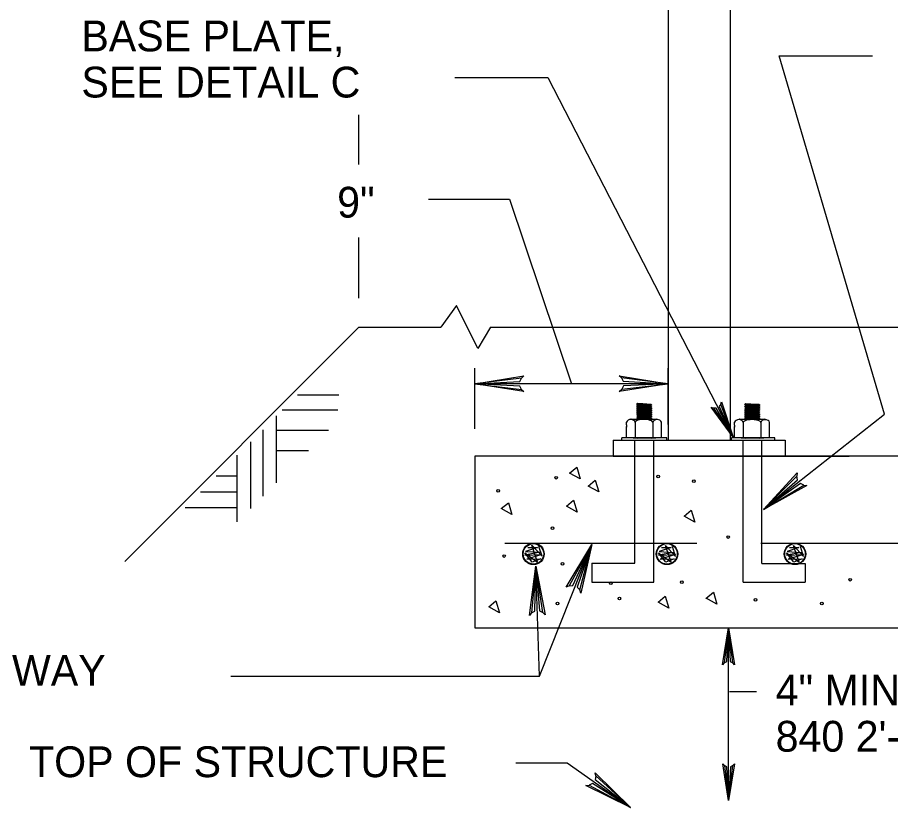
# Model space of a CAD drawing. Extents: x 637628 to 640188, y 298266 to 300751.
# Drawn here: x 638042.5 to 638127.6, y 298943.4 to 299020.4 of the extents above; entities that cross this region are included whole.
import ezdxf

# ---------------------------------------------------------------- set-up
doc = ezdxf.new("R2010")
doc.units = 0
for name, color, linetype in [('1', 7, 'Continuous'), ('2', 7, 'Continuous'), ('3', 7, 'Continuous')]:
    doc.layers.add(name, color=color, linetype=linetype)

msp = doc.modelspace()

# ---------------------------------------------------------------- linework, layer by layer
at = {"layer": '1'}
for p, q in [((638127.052, 298981.742), (638116.764, 299016.653)), ((638115.246, 298972.466), (638127.052, 298981.742))]:
    msp.add_line(p, q, dxfattribs=at)
at = {"layer": '2'}
for p, q in [((638105.949, 299059.25), (638105.949, 298979.219)), ((638105.949, 299059.25), (638105.949, 298979.219)), ((638111.99, 299059.25), (638111.99, 298979.219)), ((638111.99, 299059.25), (638111.99, 298979.219)), ((638116.764, 299016.653), (638125.872, 299016.653)), ((638085.156, 299014.527), (638094.215, 299014.527)), ((638094.215, 299014.527), (638112.272, 298979.5)), ((638075.776, 299006.064), (638075.776, 299010.894)), ((638082.581, 299002.68), (638090.48, 299002.68)), ((638090.48, 299002.68), (638096.54, 298984.707)), ((638075.776, 298993.04), (638075.776, 298998.948)), ((638085.313, 298992.317), (638083.784, 298990.205)), ((638085.313, 298992.317), (638083.784, 298990.205)), ((638087.407, 298988.136), (638085.313, 298992.317)), ((638087.407, 298988.136), (638085.313, 298992.317)), ((638075.776, 298990.205), (638052.972, 298967.4)), ((638075.776, 298990.205), (638083.784, 298990.205)), ((638075.776, 298990.205), (638083.784, 298990.205)), ((638088.632, 298990.205), (638087.407, 298988.136)), ((638088.632, 298990.205), (638087.407, 298988.136)), ((638088.632, 298990.205), (638220.882, 298990.205)), ((638088.632, 298990.205), (638207.774, 298990.205)), ((638118.24, 298990.205), (638123.599, 298990.205)), ((638118.24, 298990.205), (638123.599, 298990.205)), ((638087.115, 298980.317), (638087.115, 298986.207)), ((638105.949, 298980.719), (638105.949, 298986.207)), ((638105.949, 298984.707), (638087.115, 298984.707)), ((638073.826, 298983.575), (638069.813, 298983.575)), ((638073.826, 298983.575), (638069.813, 298983.575)), ((638102.953, 298982.767), (638102.897, 298982.734)), ((638102.897, 298982.734), (638104.345, 298982.661)), ((638102.897, 298982.709), (638104.345, 298982.638)), ((638102.897, 298982.709), (638102.999, 298982.648)), ((638102.953, 298982.575), (638102.897, 298982.542)), ((638102.999, 298982.794), (638102.953, 298982.767)), ((638102.999, 298982.602), (638102.953, 298982.575)), ((638102.999, 298982.794), (638103.474, 298982.767)), ((638102.999, 298982.648), (638104.242, 298982.575)), ((638102.999, 298982.648), (638104.242, 298982.575)), ((638102.999, 298982.602), (638103.474, 298982.575)), ((638103.474, 298982.767), (638104.242, 298982.723)), ((638103.474, 298982.575), (638104.242, 298982.532)), ((638104.242, 298982.723), (638104.345, 298982.661)), ((638104.345, 298982.638), (638104.242, 298982.575)), ((638104.345, 298982.638), (638104.345, 298982.661)), ((638113.484, 298982.752), (638113.428, 298982.719)), ((638113.428, 298982.719), (638114.876, 298982.646)), ((638113.428, 298982.694), (638114.876, 298982.623)), ((638113.428, 298982.694), (638113.53, 298982.634)), ((638113.484, 298982.561), (638113.428, 298982.527)), ((638113.53, 298982.78), (638113.484, 298982.752)), ((638113.53, 298982.588), (638113.484, 298982.561)), ((638113.53, 298982.78), (638114.005, 298982.752)), ((638113.53, 298982.634), (638114.774, 298982.561)), ((638113.53, 298982.634), (638114.774, 298982.561)), ((638113.53, 298982.588), (638114.005, 298982.561)), ((638114.005, 298982.752), (638114.774, 298982.709)), ((638114.005, 298982.561), (638114.774, 298982.517)), ((638114.774, 298982.709), (638114.876, 298982.646)), ((638114.876, 298982.623), (638114.774, 298982.561)), ((638114.876, 298982.623), (638114.876, 298982.646)), ((638073.73, 298982.132), (638068.317, 298982.132)), ((638073.73, 298982.132), (638068.317, 298982.132)), ((638102.897, 298982.542), (638104.345, 298982.469)), ((638102.897, 298982.519), (638104.345, 298982.446)), ((638102.897, 298982.519), (638102.999, 298982.457)), ((638102.953, 298982.386), (638102.897, 298982.35)), ((638102.897, 298982.35), (638104.345, 298982.28)), ((638102.897, 298982.327), (638104.345, 298982.255)), ((638102.897, 298982.327), (638102.999, 298982.265)), ((638102.953, 298982.194), (638102.897, 298982.161)), ((638102.897, 298982.161), (638104.345, 298982.088)), ((638102.897, 298982.136), (638104.345, 298982.065)), ((638102.897, 298982.136), (638102.999, 298982.075)), ((638102.953, 298982.002), (638102.897, 298981.969)), ((638102.897, 298981.969), (638104.345, 298981.898)), ((638102.897, 298981.946), (638104.345, 298981.873)), ((638102.897, 298981.946), (638102.999, 298981.884)), ((638102.953, 298981.813), (638102.897, 298981.78)), ((638102.897, 298981.78), (638104.345, 298981.707)), ((638102.897, 298981.755), (638104.345, 298981.684)), ((638102.897, 298981.755), (638102.999, 298981.694)), ((638102.999, 298982.413), (638102.953, 298982.386)), ((638102.999, 298982.221), (638102.953, 298982.194)), ((638102.999, 298982.032), (638102.953, 298982.002)), ((638102.999, 298981.84), (638102.953, 298981.813)), ((638102.999, 298982.457), (638104.242, 298982.386)), ((638102.999, 298982.457), (638104.242, 298982.386)), ((638102.999, 298982.413), (638103.474, 298982.386)), ((638102.999, 298982.265), (638104.242, 298982.194)), ((638102.999, 298982.265), (638104.242, 298982.194)), ((638102.999, 298982.221), (638103.474, 298982.194)), ((638102.999, 298982.075), (638104.242, 298982.002)), ((638102.999, 298982.075), (638104.242, 298982.002)), ((638102.999, 298982.032), (638103.474, 298982.002)), ((638102.999, 298981.884), (638104.242, 298981.813)), ((638102.999, 298981.884), (638104.242, 298981.813)), ((638102.999, 298981.84), (638103.474, 298981.813)), ((638102.999, 298981.694), (638104.242, 298981.621)), ((638102.999, 298981.694), (638104.242, 298981.621)), ((638103.474, 298982.386), (638104.242, 298982.34)), ((638103.474, 298982.194), (638104.242, 298982.15)), ((638103.474, 298982.002), (638104.242, 298981.959)), ((638103.474, 298981.813), (638104.242, 298981.769)), ((638104.242, 298982.532), (638104.345, 298982.469)), ((638104.345, 298982.446), (638104.242, 298982.386)), ((638104.242, 298982.34), (638104.345, 298982.28)), ((638104.345, 298982.255), (638104.242, 298982.194)), ((638104.242, 298982.15), (638104.345, 298982.088)), ((638104.345, 298982.065), (638104.242, 298982.002)), ((638104.242, 298981.959), (638104.345, 298981.898)), ((638104.345, 298981.873), (638104.242, 298981.813)), ((638104.242, 298981.769), (638104.345, 298981.707)), ((638104.345, 298982.446), (638104.345, 298982.469)), ((638104.345, 298982.255), (638104.345, 298982.28)), ((638104.345, 298982.065), (638104.345, 298982.088)), ((638104.345, 298981.873), (638104.345, 298981.898)), ((638104.345, 298981.684), (638104.345, 298981.707)), ((638113.428, 298982.527), (638114.876, 298982.457)), ((638113.428, 298982.502), (638114.876, 298982.432)), ((638113.428, 298982.502), (638113.53, 298982.442)), ((638113.484, 298982.371), (638113.428, 298982.336)), ((638113.428, 298982.336), (638114.876, 298982.265)), ((638113.428, 298982.313), (638114.876, 298982.24)), ((638113.428, 298982.313), (638113.53, 298982.25)), ((638113.484, 298982.18), (638113.428, 298982.146)), ((638113.428, 298982.146), (638114.876, 298982.073)), ((638113.428, 298982.121), (638114.876, 298982.05)), ((638113.428, 298982.121), (638113.53, 298982.061)), ((638113.484, 298981.988), (638113.428, 298981.955)), ((638113.428, 298981.955), (638114.876, 298981.884)), ((638113.428, 298981.932), (638114.876, 298981.859)), ((638113.428, 298981.932), (638113.53, 298981.869)), ((638113.484, 298981.798), (638113.428, 298981.763)), ((638113.428, 298981.763), (638114.876, 298981.692)), ((638113.428, 298981.74), (638114.876, 298981.669)), ((638113.428, 298981.74), (638113.53, 298981.677)), ((638113.53, 298982.398), (638113.484, 298982.371)), ((638113.53, 298982.207), (638113.484, 298982.18)), ((638113.53, 298982.017), (638113.484, 298981.988)), ((638113.53, 298981.825), (638113.484, 298981.798)), ((638113.53, 298982.442), (638114.774, 298982.371)), ((638113.53, 298982.442), (638114.774, 298982.371)), ((638113.53, 298982.398), (638114.005, 298982.371)), ((638113.53, 298982.25), (638114.774, 298982.18)), ((638113.53, 298982.25), (638114.774, 298982.18)), ((638113.53, 298982.207), (638114.005, 298982.18)), ((638113.53, 298982.061), (638114.774, 298981.988)), ((638113.53, 298982.061), (638114.774, 298981.988)), ((638113.53, 298982.017), (638114.005, 298981.988)), ((638113.53, 298981.869), (638114.774, 298981.798)), ((638113.53, 298981.869), (638114.774, 298981.798)), ((638113.53, 298981.825), (638114.005, 298981.798)), ((638114.005, 298982.371), (638114.774, 298982.325)), ((638114.005, 298982.18), (638114.774, 298982.136)), ((638114.005, 298981.988), (638114.774, 298981.944)), ((638114.005, 298981.798), (638114.774, 298981.755)), ((638114.774, 298982.517), (638114.876, 298982.457)), ((638114.876, 298982.432), (638114.774, 298982.371)), ((638114.774, 298982.325), (638114.876, 298982.265)), ((638114.876, 298982.24), (638114.774, 298982.18)), ((638114.774, 298982.136), (638114.876, 298982.073)), ((638114.876, 298982.05), (638114.774, 298981.988)), ((638114.774, 298981.944), (638114.876, 298981.884)), ((638114.876, 298981.859), (638114.774, 298981.798)), ((638114.774, 298981.755), (638114.876, 298981.692)), ((638114.876, 298982.432), (638114.876, 298982.457)), ((638114.876, 298982.24), (638114.876, 298982.265)), ((638114.876, 298982.05), (638114.876, 298982.073)), ((638114.876, 298981.859), (638114.876, 298981.884)), ((638067.751, 298975.044), (638067.751, 298981.565)), ((638067.751, 298975.044), (638067.751, 298981.565)), ((638101.89, 298980.688), (638101.89, 298980.963)), ((638102.357, 298981.267), (638104.83, 298981.267)), ((638102.73, 298980.94), (638102.73, 298979.442)), ((638102.953, 298981.621), (638102.897, 298981.588)), ((638102.897, 298981.588), (638104.345, 298981.515)), ((638102.897, 298981.563), (638104.345, 298981.492)), ((638102.897, 298981.563), (638102.999, 298981.502)), ((638102.953, 298981.432), (638102.897, 298981.396)), ((638102.897, 298981.396), (638104.345, 298981.325)), ((638102.897, 298981.373), (638104.345, 298981.3)), ((638102.897, 298981.373), (638102.999, 298981.311)), ((638102.999, 298981.648), (638102.953, 298981.621)), ((638102.999, 298981.459), (638102.953, 298981.432)), ((638102.999, 298981.267), (638102.953, 298981.24)), ((638102.999, 298981.648), (638103.474, 298981.621)), ((638102.999, 298981.502), (638104.242, 298981.432)), ((638102.999, 298981.502), (638104.242, 298981.432)), ((638102.999, 298981.459), (638103.474, 298981.432)), ((638102.999, 298981.311), (638104.242, 298981.24)), ((638102.999, 298981.311), (638104.242, 298981.24)), ((638102.999, 298981.267), (638103.474, 298981.24)), ((638103.474, 298981.621), (638104.242, 298981.577)), ((638103.474, 298981.432), (638104.242, 298981.386)), ((638104.345, 298981.684), (638104.242, 298981.621)), ((638104.242, 298981.577), (638104.345, 298981.515)), ((638104.345, 298981.492), (638104.242, 298981.432)), ((638104.242, 298981.386), (638104.345, 298981.325)), ((638104.345, 298981.3), (638104.242, 298981.24)), ((638104.345, 298981.492), (638104.345, 298981.515)), ((638104.345, 298981.3), (638104.345, 298981.325)), ((638104.457, 298980.932), (638104.457, 298979.442)), ((638105.295, 298979.442), (638105.295, 298980.952)), ((638112.422, 298980.673), (638112.422, 298980.948)), ((638112.888, 298981.252), (638115.361, 298981.252)), ((638113.261, 298980.925), (638113.261, 298979.427)), ((638113.484, 298981.607), (638113.428, 298981.573)), ((638113.428, 298981.573), (638114.876, 298981.5)), ((638113.428, 298981.548), (638114.876, 298981.477)), ((638113.428, 298981.548), (638113.53, 298981.488)), ((638113.484, 298981.415), (638113.428, 298981.382)), ((638113.428, 298981.382), (638114.876, 298981.311)), ((638113.428, 298981.359), (638114.876, 298981.286)), ((638113.428, 298981.359), (638113.53, 298981.296)), ((638113.53, 298981.634), (638113.484, 298981.607)), ((638113.53, 298981.444), (638113.484, 298981.415)), ((638113.53, 298981.252), (638113.484, 298981.225)), ((638113.53, 298981.677), (638114.774, 298981.607)), ((638113.53, 298981.677), (638114.774, 298981.607)), ((638113.53, 298981.634), (638114.005, 298981.607)), ((638113.53, 298981.488), (638114.774, 298981.415)), ((638113.53, 298981.488), (638114.774, 298981.415)), ((638113.53, 298981.444), (638114.005, 298981.415)), ((638113.53, 298981.296), (638114.774, 298981.225)), ((638113.53, 298981.296), (638114.774, 298981.225)), ((638113.53, 298981.252), (638114.005, 298981.225)), ((638114.005, 298981.607), (638114.774, 298981.563)), ((638114.005, 298981.415), (638114.774, 298981.371)), ((638114.876, 298981.669), (638114.774, 298981.607)), ((638114.774, 298981.563), (638114.876, 298981.5)), ((638114.876, 298981.477), (638114.774, 298981.415)), ((638114.774, 298981.371), (638114.876, 298981.311)), ((638114.876, 298981.286), (638114.774, 298981.225)), ((638114.876, 298981.669), (638114.876, 298981.692)), ((638114.876, 298981.477), (638114.876, 298981.5)), ((638114.876, 298981.286), (638114.876, 298981.311)), ((638114.988, 298980.917), (638114.988, 298979.427)), ((638115.826, 298979.427), (638115.826, 298980.938)), ((638066.451, 298973.738), (638066.451, 298980.215)), ((638066.451, 298973.738), (638066.451, 298980.215)), ((638072.847, 298980.132), (638067.811, 298980.132)), ((638072.847, 298980.132), (638067.811, 298980.132)), ((638101.89, 298980.688), (638101.89, 298980.488)), ((638101.89, 298979.442), (638101.89, 298980.546)), ((638112.422, 298980.673), (638112.422, 298980.471)), ((638112.422, 298979.427), (638112.422, 298980.532)), ((638100.584, 298979.219), (638100.584, 298977.65)), ((638100.584, 298979.219), (638100.584, 298977.65)), ((638100.584, 298979.219), (638105.57, 298979.219)), ((638100.584, 298979.219), (638101.884, 298979.219)), ((638105.815, 298979.442), (638101.44, 298979.442)), ((638101.44, 298979.242), (638101.44, 298979.442)), ((638102.534, 298979.444), (638104.751, 298979.444)), ((638102.534, 298979.444), (638104.751, 298979.444)), ((638102.709, 298967.217), (638102.709, 298979.215)), ((638102.709, 298967.217), (638102.709, 298979.215)), ((638102.897, 298979.463), (638102.999, 298979.402)), ((638104.242, 298979.477), (638104.345, 298979.417)), ((638104.54, 298965.367), (638104.54, 298979.215)), ((638104.54, 298967.207), (638104.54, 298979.215)), ((638105.57, 298979.219), (638117.349, 298979.219)), ((638105.57, 298979.219), (638117.349, 298979.219)), ((638105.815, 298979.248), (638105.815, 298979.442)), ((638116.349, 298979.427), (638112.111, 298979.427)), ((638112.111, 298979.248), (638112.111, 298979.427)), ((638113.065, 298979.43), (638115.282, 298979.43)), ((638113.065, 298979.43), (638115.282, 298979.43)), ((638113.249, 298967.188), (638113.249, 298979.223)), ((638113.249, 298965.363), (638113.249, 298979.213)), ((638113.428, 298979.45), (638113.53, 298979.388)), ((638114.774, 298979.463), (638114.876, 298979.402)), ((638115.082, 298967.188), (638115.082, 298979.223)), ((638115.082, 298967.188), (638115.082, 298979.223)), ((638116.349, 298979.234), (638116.349, 298979.427)), ((638117.349, 298979.219), (638117.349, 298977.65)), ((638065.272, 298972.557), (638065.272, 298979.034)), ((638065.272, 298972.557), (638065.272, 298979.034)), ((638063.942, 298971.236), (638063.945, 298977.757)), ((638063.942, 298971.236), (638063.945, 298977.757)), ((638070.895, 298978.18), (638067.838, 298978.18)), ((638070.895, 298978.18), (638067.838, 298978.18)), ((638100.584, 298977.65), (638123.599, 298977.65)), ((638100.584, 298977.65), (638123.599, 298977.65)), ((638063.936, 298975.696), (638061.884, 298975.696)), ((638063.936, 298975.696), (638061.884, 298975.696)), ((638063.959, 298974.13), (638060.365, 298974.13)), ((638063.959, 298974.13), (638060.365, 298974.13)), ((638063.934, 298972.611), (638058.849, 298972.611)), ((638063.934, 298972.611), (638058.849, 298972.611)), ((638090.011, 298969.177), (638108.742, 298969.177)), ((638093.224, 298967.321), (638092.655, 298968.961)), ((638092.655, 298968.961), (638093.655, 298967.89)), ((638092.815, 298969.177), (638105.892, 298969.177)), ((638106.245, 298967.315), (638105.676, 298968.955)), ((638105.676, 298968.955), (638106.676, 298967.886)), ((638114.986, 298969.177), (638134.967, 298969.177)), ((638118.722, 298967.315), (638118.151, 298968.955)), ((638118.151, 298968.955), (638119.151, 298967.886)), ((638118.274, 298969.177), (638131.351, 298969.177)), ((638093.463, 298968.282), (638091.984, 298968)), ((638092.695, 298967.321), (638091.984, 298968.232)), ((638091.984, 298968.232), (638093.224, 298967.321)), ((638093.205, 298968.75), (638092.055, 298968.361)), ((638092.055, 298968.361), (638093.463, 298968.282)), ((638092.263, 298968.75), (638093.205, 298968.75)), ((638092.813, 298968.132), (638092.813, 298968.132)), ((638093.655, 298967.89), (638093.355, 298968.861)), ((638106.484, 298968.275), (638105.005, 298967.994)), ((638105.715, 298967.315), (638105.005, 298968.225)), ((638105.005, 298968.225), (638106.245, 298967.315)), ((638106.226, 298968.744), (638105.076, 298968.355)), ((638105.076, 298968.355), (638106.484, 298968.275)), ((638105.284, 298968.744), (638106.226, 298968.744)), ((638105.834, 298968.125), (638105.834, 298968.125)), ((638106.676, 298967.886), (638106.376, 298968.855)), ((638118.961, 298968.275), (638117.482, 298967.996)), ((638118.192, 298967.315), (638117.482, 298968.225)), ((638117.482, 298968.225), (638118.722, 298967.315)), ((638118.701, 298968.746), (638117.551, 298968.355)), ((638117.551, 298968.355), (638118.961, 298968.275)), ((638117.761, 298968.746), (638118.701, 298968.746)), ((638118.311, 298968.125), (638118.311, 298968.125)), ((638119.151, 298967.886), (638118.851, 298968.855)), ((638091.984, 298968), (638093.634, 298968.061)), ((638093.634, 298968.061), (638092.163, 298967.611)), ((638092.163, 298967.611), (638093.524, 298967.64)), ((638093.524, 298967.64), (638092.695, 298967.321)), ((638105.005, 298967.994), (638106.655, 298968.055)), ((638106.655, 298968.055), (638105.184, 298967.605)), ((638105.184, 298967.605), (638106.545, 298967.636)), ((638106.545, 298967.636), (638105.715, 298967.315)), ((638117.482, 298967.996), (638119.132, 298968.055)), ((638119.132, 298968.055), (638117.661, 298967.605)), ((638117.661, 298967.605), (638119.022, 298967.636)), ((638119.022, 298967.636), (638118.192, 298967.315)), ((638098.497, 298967.217), (638098.497, 298965.367)), ((638098.497, 298967.217), (638102.709, 298967.217)), ((638115.082, 298967.188), (638119.292, 298967.188)), ((638119.292, 298967.188), (638119.292, 298965.363)), ((638098.497, 298965.367), (638104.54, 298965.367)), ((638113.249, 298965.363), (638119.292, 298965.363)), ((638087.115, 298960.913), (638187.549, 298960.913)), ((638111.838, 298944.105), (638111.838, 298960.913)), ((638111.929, 298954.713), (638114.567, 298954.713))]:
    msp.add_line(p, q, dxfattribs=at)
for points in [[(638091.657, 298984.136), (638091.488, 298984.465), (638087.115, 298984.707), (638091.657, 298984.136), (638091.89, 298983.936), (638087.115, 298984.707), (638091.484, 298984.921), (638091.645, 298985.246), (638087.115, 298984.707), (638091.89, 298985.465), (638091.645, 298985.246)], [(638101.407, 298985.275), (638101.576, 298984.946), (638105.949, 298984.707), (638101.407, 298985.275), (638101.174, 298985.475), (638105.949, 298984.707), (638101.58, 298984.49), (638101.42, 298984.165), (638105.949, 298984.707), (638101.174, 298983.946), (638101.42, 298984.165)], [(638102.897, 298982.709), (638102.897, 298982.734)], [(638102.999, 298982.602), (638102.999, 298982.648)], [(638104.242, 298982.532), (638104.242, 298982.575)], [(638111.09, 298982.723), (638110.93, 298982.496), (638112.272, 298979.5), (638111.09, 298982.723), (638111.145, 298982.946), (638112.272, 298979.5), (638110.626, 298982.338), (638110.355, 298982.332), (638112.272, 298979.5), (638110.126, 298982.421), (638110.355, 298982.332)], [(638113.428, 298982.694), (638113.428, 298982.719)], [(638113.53, 298982.588), (638113.53, 298982.634)], [(638114.774, 298982.517), (638114.774, 298982.561)], [(638102.897, 298982.519), (638102.897, 298982.542)], [(638102.897, 298982.327), (638102.897, 298982.35)], [(638102.897, 298982.136), (638102.897, 298982.161)], [(638102.897, 298981.946), (638102.897, 298981.969)], [(638102.897, 298981.755), (638102.897, 298981.78)], [(638102.999, 298982.413), (638102.999, 298982.457)], [(638102.999, 298982.221), (638102.999, 298982.265)], [(638102.999, 298982.032), (638102.999, 298982.075)], [(638102.999, 298981.84), (638102.999, 298981.884)], [(638102.999, 298981.648), (638102.999, 298981.694)], [(638104.242, 298982.34), (638104.242, 298982.386)], [(638104.242, 298982.15), (638104.242, 298982.194)], [(638104.242, 298981.959), (638104.242, 298982.002)], [(638104.242, 298981.769), (638104.242, 298981.813)], [(638113.428, 298982.502), (638113.428, 298982.527)], [(638113.428, 298982.313), (638113.428, 298982.336)], [(638113.428, 298982.121), (638113.428, 298982.146)], [(638113.428, 298981.932), (638113.428, 298981.955)], [(638113.428, 298981.74), (638113.428, 298981.763)], [(638113.53, 298982.398), (638113.53, 298982.442)], [(638113.53, 298982.207), (638113.53, 298982.25)], [(638113.53, 298982.017), (638113.53, 298982.061)], [(638113.53, 298981.825), (638113.53, 298981.869)], [(638114.774, 298982.325), (638114.774, 298982.371)], [(638114.774, 298982.136), (638114.774, 298982.18)], [(638114.774, 298981.944), (638114.774, 298981.988)], [(638114.774, 298981.755), (638114.774, 298981.798)], [(638102.897, 298981.563), (638102.897, 298981.588)], [(638102.897, 298981.373), (638102.897, 298981.396)], [(638102.999, 298981.459), (638102.999, 298981.502)], [(638102.999, 298981.267), (638102.999, 298981.311)], [(638104.242, 298981.577), (638104.242, 298981.621)], [(638104.242, 298981.386), (638104.242, 298981.432)], [(638113.428, 298981.548), (638113.428, 298981.573)], [(638113.428, 298981.359), (638113.428, 298981.382)], [(638113.53, 298981.634), (638113.53, 298981.677)], [(638113.53, 298981.444), (638113.53, 298981.488)], [(638113.53, 298981.252), (638113.53, 298981.296)], [(638114.774, 298981.563), (638114.774, 298981.607)], [(638114.774, 298981.371), (638114.774, 298981.415)], [(638102.897, 298979.463), (638102.897, 298979.488)], [(638113.428, 298979.45), (638113.428, 298979.473)], [(638087.115, 298977.65), (638087.115, 298960.913), (638088.938, 298960.913)], [(638087.115, 298977.65), (638087.115, 298960.913), (638088.938, 298960.913)], [(638087.815, 298960.913), (638187.549, 298960.913), (638187.549, 298977.65), (638087.115, 298977.65)], [(638096.344, 298976), (638097.035, 298976.578), (638097.383, 298975.423), (638096.344, 298976)], [(638119.173, 298974.816), (638118.836, 298974.972), (638115.246, 298972.466), (638119.173, 298974.816), (638119.479, 298974.804), (638115.246, 298972.466), (638118.553, 298975.329), (638118.478, 298975.684), (638115.246, 298972.466), (638118.536, 298976.008), (638118.478, 298975.684)], [(638098.153, 298974.74), (638098.847, 298975.321), (638099.195, 298974.161), (638098.153, 298974.74)], [(638098.153, 298974.74), (638098.847, 298975.321), (638099.195, 298974.161), (638098.153, 298974.74)], [(638096.024, 298972.772), (638096.72, 298973.352), (638097.066, 298972.195), (638096.024, 298972.772)], [(638089.682, 298972.536), (638090.376, 298973.115), (638090.722, 298971.959), (638089.682, 298972.536)], [(638107.504, 298971.796), (638108.195, 298972.379), (638108.543, 298971.219), (638107.504, 298971.796)], [(638063.312, 298956.223), (638093.401, 298956.223), (638098.495, 298969.032)], [(638096.286, 298965.023), (638096.655, 298965.059), (638098.495, 298969.032), (638096.286, 298965.023), (638096.015, 298964.88), (638098.495, 298969.032), (638097.08, 298964.892), (638097.324, 298964.623), (638098.495, 298969.032), (638097.436, 298964.315), (638097.324, 298964.623)], [(638092.624, 298962.369), (638092.947, 298962.548), (638093.04, 298966.925), (638092.624, 298962.369), (638092.432, 298962.13), (638093.04, 298966.925), (638093.403, 298962.567), (638093.734, 298962.419), (638093.04, 298966.925), (638093.959, 298962.18), (638093.734, 298962.419)], [(638093.401, 298956.223), (638093.04, 298966.925)], [(638104.978, 298963.409), (638105.67, 298963.992), (638106.017, 298962.832), (638104.978, 298963.409)], [(638104.978, 298963.409), (638105.67, 298963.992), (638106.017, 298962.832), (638104.978, 298963.409)], [(638109.608, 298963.772), (638110.362, 298964.401), (638110.708, 298963.245), (638109.668, 298963.822)], [(638088.456, 298962.961), (638089.148, 298963.538), (638089.496, 298962.384), (638088.456, 298962.961)], [(638111.411, 298957.507), (638111.657, 298957.634), (638111.838, 298960.913), (638111.411, 298957.507), (638111.261, 298957.334), (638111.838, 298960.913), (638111.999, 298957.638), (638112.245, 298957.517), (638111.838, 298960.913), (638112.407, 298957.334), (638112.245, 298957.517)], [(638091.111, 298947.786), (638096.111, 298947.786), (638102.261, 298943.417)], [(638112.265, 298947.511), (638112.02, 298947.384), (638111.838, 298944.105), (638112.265, 298947.511), (638112.415, 298947.686), (638111.838, 298944.105), (638111.676, 298947.382), (638111.432, 298947.5), (638111.838, 298944.105), (638111.27, 298947.686), (638111.432, 298947.5)], [(638098.89, 298946.511), (638098.838, 298946.146), (638102.261, 298943.417), (638098.89, 298946.511), (638098.815, 298946.809), (638102.261, 298943.417), (638098.576, 298945.771), (638098.257, 298945.598), (638102.261, 298943.417), (638097.932, 298945.563), (638098.257, 298945.598)]]:
    msp.add_lwpolyline(points, dxfattribs=at)
for centre, radius in [((638104.976, 298975.666), 0.129), ((638104.976, 298975.666), 0.129), ((638095.035, 298975.551), 0.129), ((638095.035, 298975.551), 0.129), ((638108.443, 298975.203), 0.129), ((638108.443, 298975.203), 0.129), ((638089.372, 298974.277), 0.129), ((638089.372, 298974.277), 0.129), ((638094.678, 298970.634), 0.129), ((638111.793, 298969.77), 0.129), ((638111.793, 298969.77), 0.129), ((638092.814, 298968.131), 1.046), ((638092.814, 298968.131), 1.046), ((638092.814, 298968.131), 1), ((638105.835, 298968.125), 1.046), ((638105.835, 298968.125), 1.046), ((638105.835, 298968.125), 1), ((638118.312, 298968.125), 1.046), ((638118.312, 298968.125), 1.046), ((638118.312, 298968.125), 1), ((638089.949, 298967.918), 0.129), ((638089.949, 298967.918), 0.129), ((638095.644, 298967.157), 0.129), ((638123.7, 298965.61), 0.129), ((638123.7, 298965.61), 0.129), ((638100.354, 298965.263), 0.129), ((638107.284, 298965.378), 0.129), ((638107.284, 298965.378), 0.129), ((638101.191, 298963.782), 0.129), ((638095.151, 298963.294), 0.129), ((638095.151, 298963.294), 0.129), ((638114.454, 298963.641), 0.129), ((638114.454, 298963.641), 0.129), ((638120.922, 298963.294), 0.129), ((638120.922, 298963.294), 0.129)]:
    msp.add_circle(centre, radius, dxfattribs=at)
for centre, start, end in [((638102.356, 298981.221), 90, 180), ((638104.829, 298981.221), 0, 90), ((638112.888, 298981.207), 90, 180), ((638115.36, 298981.207), 0, 90)]:
    msp.add_arc(centre, 0.046, start, end, dxfattribs=at)
for centre, major_axis, ratio, start_param, end_param in [((638102.309, 298980.936), (0.42, 0.005), 0.679852, 0, 3.035161), ((638103.593, 298980.936), (0.863, -0.005), 0.335964, 0, 3.141593), ((638104.876, 298980.927), (-0.42, 0.005), 0.679852, 3.248025, 6.283185), ((638112.84, 298980.921), (0.42, 0.005), 0.679852, 0, 3.035161), ((638114.124, 298980.921), (0.863, -0.005), 0.335964, 0, 3.141593), ((638115.407, 298980.912), (-0.42, 0.005), 0.679852, 3.248025, 6.283185)]:
    msp.add_ellipse(centre, major_axis=major_axis, ratio=ratio, start_param=start_param, end_param=end_param, dxfattribs=at)

# ---------------------------------------------------------------- texts
at = {"layer": '3'}
for s, height, p in [('BASE PLATE,', 2.99999, (638048.741, 299017.087)), ('SEE DETAIL C', 2.99999, (638048.741, 299012.589)), ('9"', 3, (638073.678, 299000.888)), ('C TO C EACH WAY', 3, (638015.006, 298955.283)), ('4" MIN TO', 3, (638116.424, 298953.357)), ('840 2\'-9" MAX.', 2.99999, (638116.424, 298948.859)), ('TOP OF STRUCTURE', 2.99999, (638043.639, 298946.375))]:
    msp.add_text(s, height=height, dxfattribs=at).set_placement(p)

doc.saveas('drawing.dxf')
